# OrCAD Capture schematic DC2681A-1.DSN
size Custom
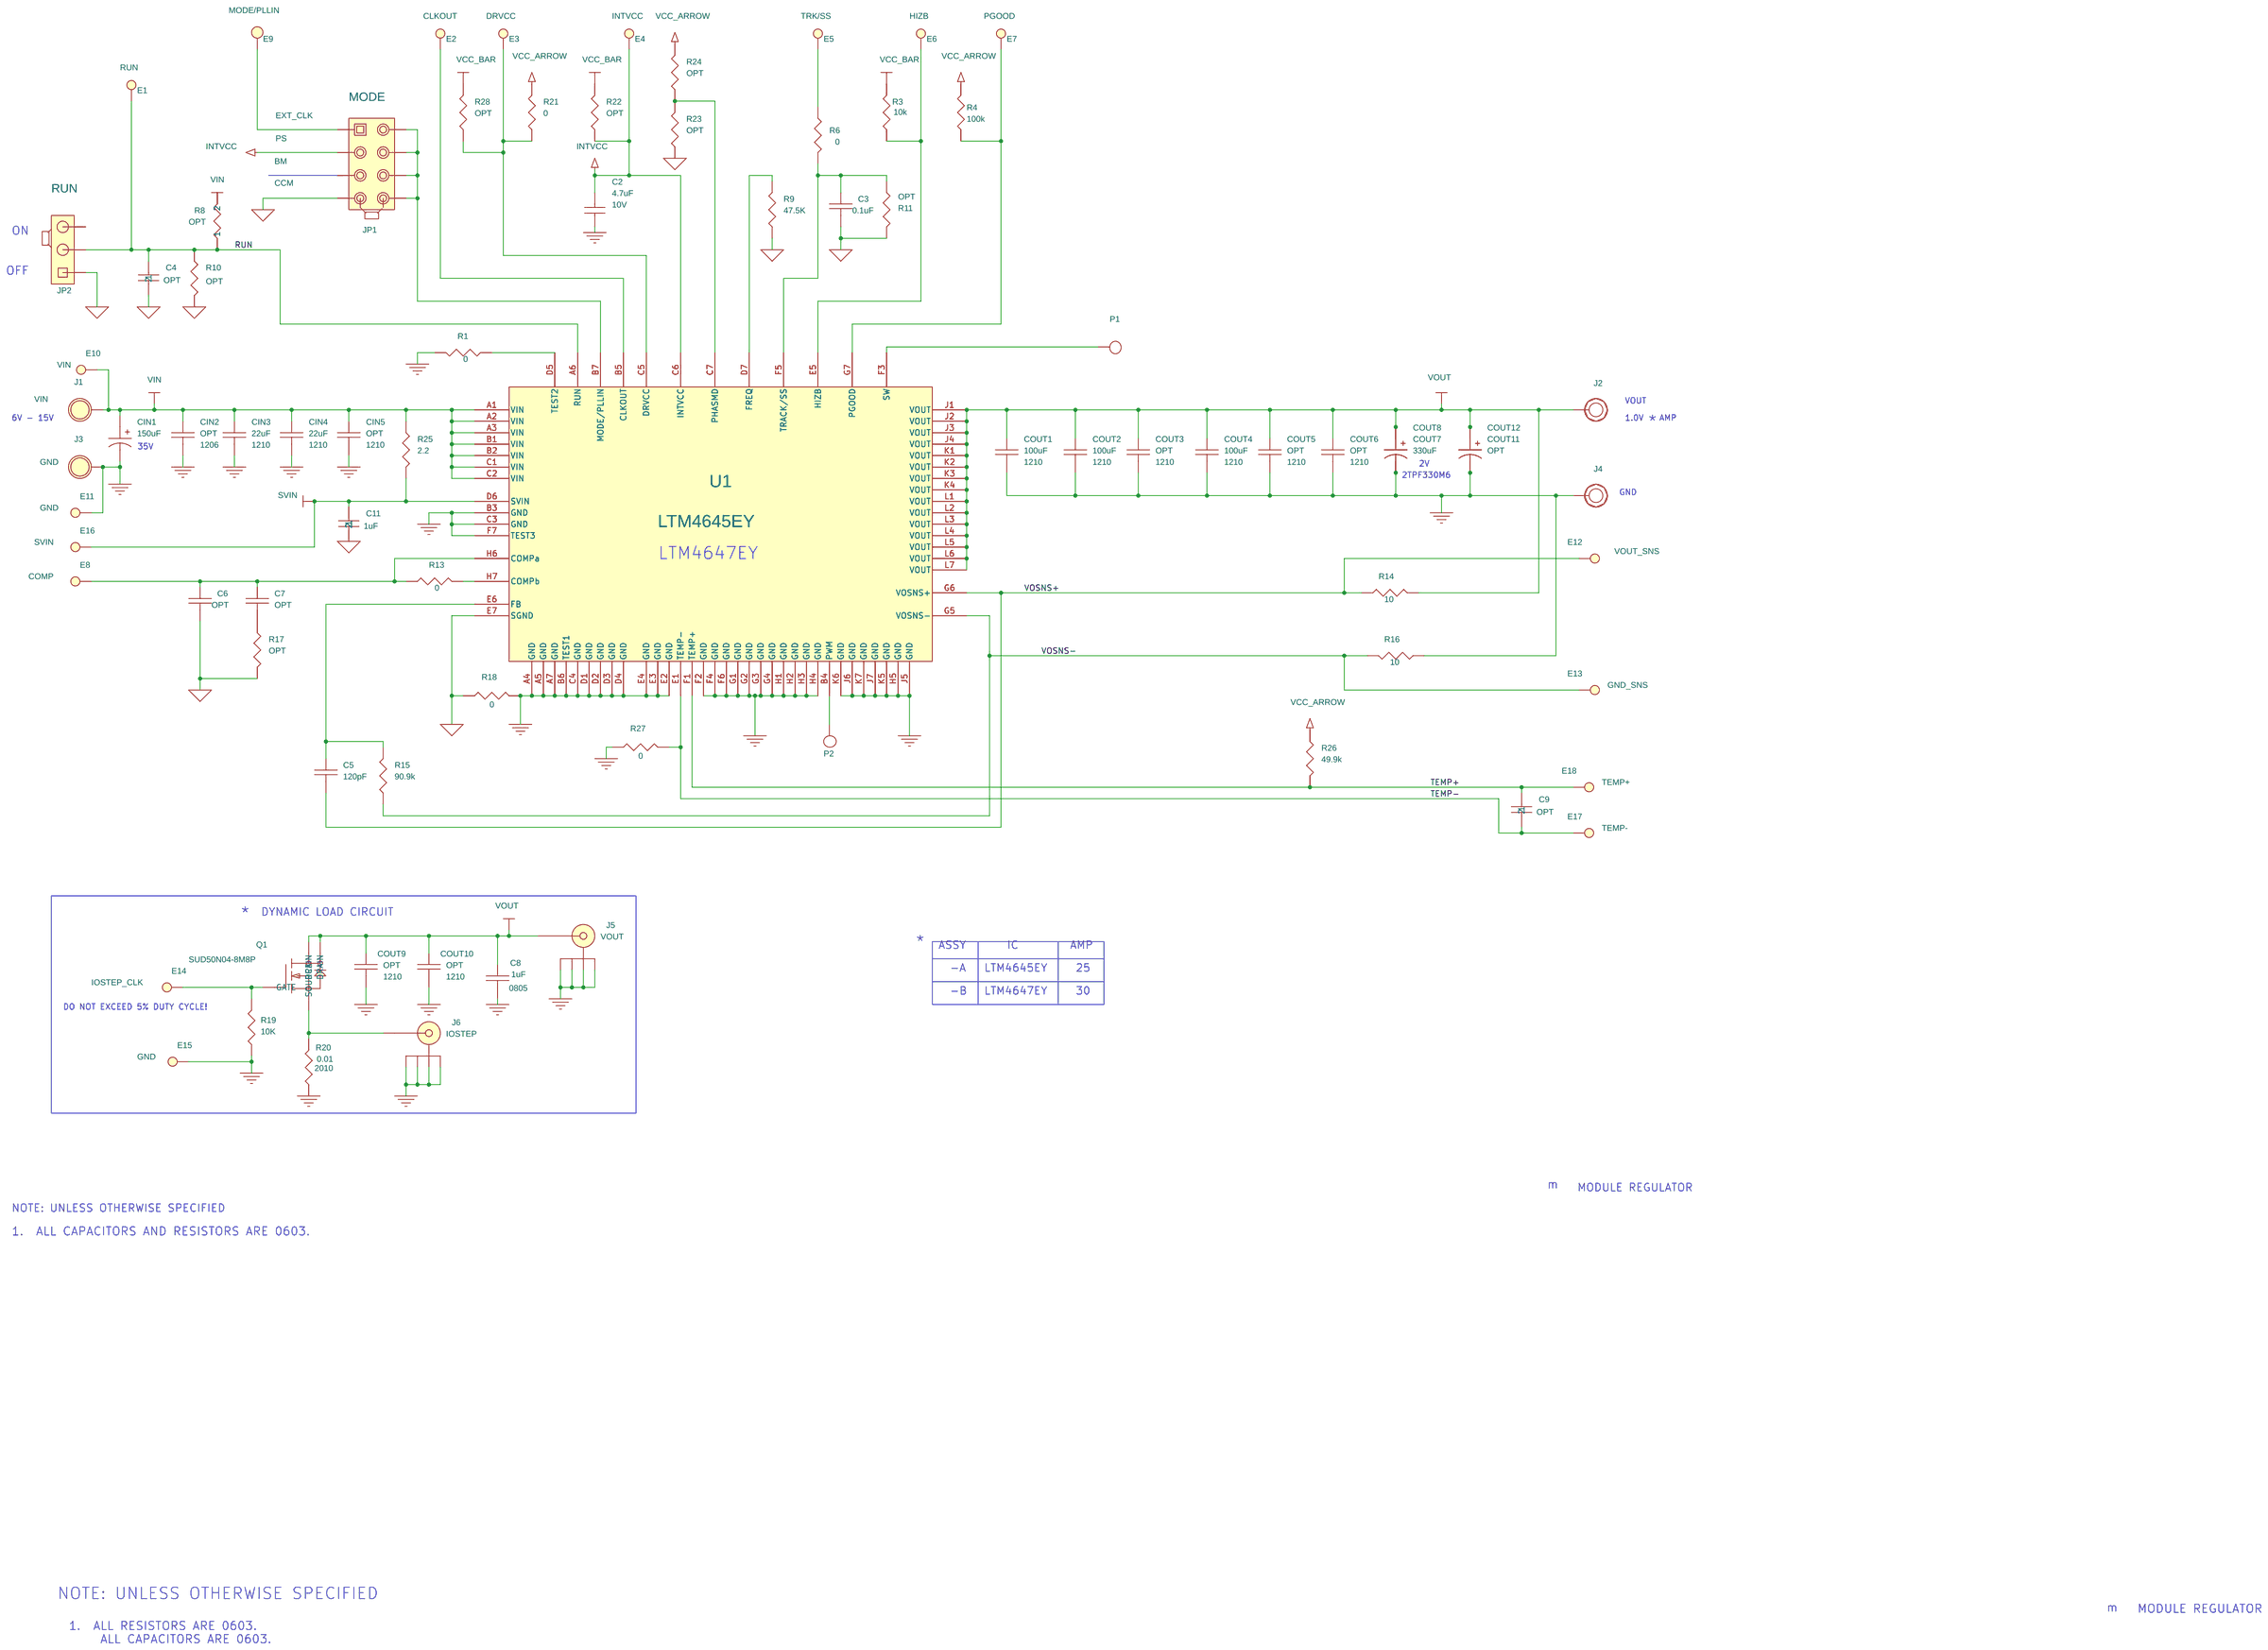
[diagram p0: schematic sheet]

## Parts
C2  4.7uF  [0603]
C3  0.1uF  [0603]
C4  OPT  [0603]
C5  120pF  [0603]
C6  OPT  [0603]
C7  OPT  [0603]
C8  1uF  [0805]
C9  OPT  [0603]
C11  1uF  [0603]
CIN1  150uF  [C-10X10.5]
CIN2  OPT  [1206]
CIN3  22uF  [1210]
CIN4  22uF  [1210]
CIN5  OPT  [1210]
COUT1  100uF  [1210]
COUT2  100uF  [1210]
COUT3  OPT  [1210]
COUT4  100uF  [1210]
COUT5  OPT  [1210]
COUT6  OPT  [1210]
COUT7  330uF  [C-D3L-D2E-D4]
COUT8  330uF  [C-D3L-D2E-D4]
COUT9  OPT  [1210]
COUT10  OPT  [1210]
COUT11  OPT  [C-D3L-D2E-D4]
COUT12  OPT  [C-D3L-D2E-D4]
E1  TURRETS  [MILL-MAX-2308]
E2  CLKOUT  [MILL-MAX-2308]
E3  DRVCC  [MILL-MAX-2308]
E4  INTVCC  [MILL-MAX-2308]
E5  TRK/SS  [MILL-MAX-2308]
E6  HIZB  [MILL-MAX-2308]
E7  PGOOD  [MILL-MAX-2308]
E8  COMP  [MILL-MAX-2308]
E9  MODE/PLLIN  [MILL-MAX-2308]
E10  TURRETS  [MILL-MAX-2308]
E11  GND  [MILL-MAX-2308]
E12  TURRETS  [MILL-MAX-2308]
E13  TURRETS  [MILL-MAX-2308]
E14  IOSTEP_CLK  [MILL-MAX-2308]
E15  GND  [MILL-MAX-2308]
E16  SVIN  [MILL-MAX-2308]
E17  TURRETS  [MILL-MAX-2308]
E18  TURRETS  [MILL-MAX-2308]
J1  BANANA SMALL  [KEY-575-4]
J2  STUD  [CON\LUG\10]
J3  BANANA SMALL  [KEY-575-4]
J4  STUD  [CON\LUG\10]
J5  VOUT  [BNC]
J6  IOSTEP  [BNC]
JP1  HD2X4-079  [HD2X4-079]
JP2  HD1X3-079  [HD1X3-079]
P1  SMD PAD  [PAD]
P2  SMD PAD  [PAD]
Q1  SUD50N04-8M8P  [TO252]
R1  0  [0603]
R3  10k  [0603]
R4  100k  [0603]
R6  0  [0603]
R8  OPT  [0603]
R9  47.5K  [0603]
R10  OPT  [0603]
R11  OPT  [0603]
R13  0  [0603]
R14  10  [0603]
R15  90.9k  [0603]
R16  10  [0603]
R17  OPT  [0603]
R18  0  [0603]
R19  10K  [0603]
R20  0.01  [2010]
R21  0  [0603]
R22  OPT  [0603]
R23  OPT  [0603]
R24  OPT  [0603]
R25  2.2  [0603]
R26  49.9k  [0603]
R27  0  [0603]
R28  OPT  [0603]
U1  LTM4645EY  [BGA77-15X9-5.01-A]
XJP1  2mm Ctrs.
XJP2  2mm Ctrs.

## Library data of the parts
C2 = CAP_NP_3: CAP, 0805 4.7uF 10% 10V X5R; Part Number: TAIYO YUDEN LMK212BJ475KG-T; Voltage: 10V
C3 C5-C7 = CAP0603_1: Component: cap; Manufacturer: TDK; Manufacturer P/N: C1608C0G1H102J; Tolerance: 5%; Type: cer 0603; Vendor: Digikey; Vendor P/N: 445-1293-1-ND; Volts/Amps/Watts: 50V
C4 = CAP_NP_1_1: CAP, 0603 0.1uF 10% 50V X7R; Part Number: TDK C1608X7R1H104K; Voltage: 50V
C8 = CAP0603_1
C9 = CAP_NP_1_2: CAP, 0603 0.1uF 10% 50V X7R; Part Number: TDK C1608X7R1H104K; Voltage: 50V
C11 = CAP_NP_1: CAP, 0603 0.1uF 10% 50V X7R; Part Number: TDK C1608X7R1H104K; Voltage: 50V
CIN1 = CAPR12X5_0: Component: cap; Manufacturer: SANYO; Tolerance: 20%; Type: OS-CON; Volts/Amps/Watts: 16V
CIN2-CIN5 = CAP1210_1: Component: cap; Manufacturer: Taiyo Yuden; Manufacturer P/N: GMK325BJ106KN-T; Tolerance: 10%; Type: cer 1210; Vendor: Digikey; Vendor P/N: 587-1439-1-ND; Volts/Amps/Watts: 25V
COUT1-COUT6 COUT9 COUT10 = CAP0603_1: Component: cap; Manufacturer: TDK; Manufacturer P/N: C3225X5R0J107M; Part Type: CAP1210; Tolerance: 20%; Type: cer 1210 X5R; Vendor: Digikey; Vendor P/N: 445-1437-1-ND; Volts/Amps/Watts: 6.3v
COUT7 COUT8 COUT11 COUT12 = CAPR12X5_0: Component: cap; Manufacturer: SANYO; Manufacturer P/N: 6TPF330M9L; Tolerance: 20%; Type: TANT; Volts/Amps/Watts: 6.3V
E1 = TURRETS_1: Component: tp; Label: RUN; Manufacturer: Keystone; Manufacturer P/N: 1593-2; Vendor: Digikey; Vendor P/N: 1593-2K-ND
E2-E8 E14 E16 = TURRETS_1: Component: tp; Label: GND; Manufacturer: Keystone; Manufacturer P/N: 1593-2; Vendor: Digikey; Vendor P/N: 1593-2K-ND
E9 = T_POINT_R_0: TURRET; Part Number: MILL-MAX 2501-2-00-80-00-00-07-0; STATUS: ?
E10 = TURRETS_1: Component: tp; Label: VIN; Manufacturer: Keystone; Manufacturer P/N: 1593-2; Vendor: Digikey; Vendor P/N: 1593-2K-ND
E11 E15 = TURRETS_1: Component: tp; Manufacturer: Keystone; Manufacturer P/N: 1593-2; Vendor: Digikey; Vendor P/N: 1593-2K-ND
E12 = TURRETS_1: Component: tp; Label: VOUT_SNS; Vendor: Digikey; Vendor P/N: 1593-2K-ND
E13 = TURRETS_1: Component: tp; Label: GND_SNS; Vendor: Digikey; Vendor P/N: 1593-2K-ND
E17 = TURRETS_1: Component: tp; Label: TEMP-; Vendor: Digikey; Vendor P/N: 1593-2K-ND
E18 = TURRETS_1: Component: tp; Label: TEMP+; Vendor: Digikey; Vendor P/N: 1593-2K-ND
J1 = BANANA_SMALL_0: Component: conn; Label: VIN
J2 J4 = E-KEY-575
J3 = BANANA_SMALL_0: Component: conn; Label: GND
J5 J6 = BNC5-SCH_0
JP1 = Samtec_TMM-103-02-L-D_0: 10th Part Field: PS; 11th Part Field: CCM; 12th Part Field: MODE; 9th Part Field: EXT_CLK; PIN5: BM
JP2 = Commcon2802s03g2_7: 11th Part Field: OFF; 12th Part Field: RUN; 9th Part Field: ON
P1 P2 = PAD_2: Component: tp; Label: <Label>; Vendor: Digikey; Vendor P/N: 1593-2K-ND
Q1 = IRF540_0
R1 R9 R13 R15 = RES0603_9: Manufacturer: Rohm; Manufacturer P/N: RHM0.0GCT-ND; Tolerance: 5%; Vendor: Digikey; Vendor P/N: RHM0.0GCT-ND; Volts/Amps/Watts: 0.1W
R3 R4 R21-R24 R28 = RES_0: RES, 0603 0 OHM JUMPER 1/10W; Part Number: VISHAY CRC06030000Z0EA; Tolerance: JUMPER
R6 R11 R17 R25 R26 = RES0603_9: Component: res; Label: <label>; Manufacturer: Panasonic; Manufacturer P/N: ERJ-3EKF5901V; Tolerance: 1%; Vendor: Digikey; Vendor P/N: P5.90KHCT-ND; Volts/Amps/Watts: 0.1W
R8 = CR16-104JM: RES, 0603 30.1k OHMS 1% 1/10W; Part Number: VISHAY CRCW060330K1FKEA
R10 = CR16-2002FM: RES, 0603 10.0k OHMS 1% 1/10W; 5th Part Field: CR16-1002FM; Part Number: VISHAY CRCW060330K1FKEA
R14 = RES0603_9: Manufacturer: Rohm; Manufacturer P/N: MCR03EZPFX1000; Vendor: Digikey; Vendor P/N: RHM100HCT-ND; Volts/Amps/Watts: 0.1W
R16 = RES0603_9: Manufacturer: Yageo; Manufacturer P/N: RC0603JR-070RL; Tolerance: 5%; Vendor: Digikey; Vendor P/N: 311-0.0GRCT-ND; Volts/Amps/Watts: 0.1W
R18 R27 = RES0603_3
R19 = RES0603_9
R20 = RES0603_5: Label: 1W; Manufacturer: VISHAY; Manufacturer P/N: CRCW251230R0JNEG; Part Type: 2512; Tolerance: 5%; Vendor: Digikey; Vendor P/N: 541-30XCT-ND; Volts/Amps/Watts: 0.1W
U1 = LTC3880-M0001_52: Component: IC; Manufacturer: LTC; Manufacturer P/N: LTC3880_M0001; Vendor: LTC; Vendor P/N: LTC3880_M0001
XJP1 XJP2 = CommconCCIJ2MM-138G

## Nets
GND_POWER: C2.2 C8.2 CIN1.2 CIN2.2 CIN3.2 CIN4.2 CIN5.2 COUT1.2 COUT2.2 COUT3.2 COUT4.2 COUT5.2 COUT6.2 COUT7.2 COUT8.2 COUT9.2 COUT10.2 COUT11.2 COUT12.2 E11.1(TP) E15.1(TP) J3.1(TP) J4.1 J5.2 J5.3 J5.4 J5.5 J6.2 J6.3 J6.4 J6.5 R1.2 R16.2 R18.2 R19.2 R20.1 R27.1 U1.A4(GND) U1.A5(GND) U1.A7(GND) U1.B3(GND) U1.B6(TEST1) U1.C3(GND) U1.C4(GND) U1.D1(GND) U1.D2(GND) U1.D3(GND) U1.D4(GND) U1.E2(GND) U1.E3(GND) U1.E4(GND) U1.F2(GND) U1.F4(GND) U1.F6(GND) U1.F7(TEST3) U1.G1(GND) U1.G2(GND) U1.G3(GND) U1.G4(GND) U1.H1(GND) U1.H2(GND) U1.H3(GND) U1.H4(GND) U1.H5(GND) U1.J5(GND) U1.J6(GND) U1.J7(GND) U1.K5(GND) U1.K6(GND) U1.K7(GND)
GND_SIGNAL: C3.2 C4.2 C6.2 C11.2 JP1.7 JP2.1 R9.2 R10.2 R11.2 R17.2 R18.1 R23.2 U1.E7(SGND)
SVIN: C11.1 E16.1(TP) R22.1 R25.2 U1.D6(SVIN)
VIN: CIN1.1 CIN2.1 CIN3.1 CIN4.1 CIN5.1 E10.1(TP) J1.1(TP) R3.1 R8.2 R25.1 R28.1 U1.A1(VIN) U1.A2(VIN) U1.A3(VIN) U1.B1(VIN) U1.B2(VIN) U1.C1(VIN) U1.C2(VIN)
INTVCC: C2.1 E4.1(TP) JP1.3 R4.1 R21.1 R22.2 R24.1 R26.1 U1.C6(INTVCC)
RUN: C4.1 E1.1(TP) JP2.2 R8.1 R10.1 U1.A6(RUN)
TEMP+: C9.1 E18.1(TP) R26.2 U1.F1(TEMP+)
TEMP-: C9.2 E17.1(TP) R27.2 U1.E1(TEMP-)
VOSNS+: C5.2 E12.1(TP) R14.1 U1.G6(VOSNS+)
VOSNS-: E13.1(TP) R15.1 R16.1 U1.G5(VOSNS-)
VOUT: C8.1 COUT1.1 COUT2.1 COUT3.1 COUT4.1 COUT5.1 COUT6.1 COUT7.1 COUT8.1 COUT9.1 COUT10.1 COUT11.1 COUT12.1 J2.1 J5.1 Q1.2(DRAIN) Q1.4(DRAIN) R14.2 U1.J1(VOUT) U1.J2(VOUT) U1.J3(VOUT) U1.J4(VOUT) U1.K1(VOUT) U1.K2(VOUT) U1.K3(VOUT) U1.K4(VOUT) U1.L1(VOUT) U1.L2(VOUT) U1.L3(VOUT) U1.L4(VOUT) U1.L5(VOUT) U1.L6(VOUT) U1.L7(VOUT)
N17156241: C6.1 C7.1 E8.1(TP) R13.2 U1.H6(COMPa)
N18445914: E14.1(TP) Q1.1(GATE) R19.1
N18446004: J6.1 Q1.3(SOURCE) R20.2
N18545248: JP1.2 JP1.4 JP1.6 JP1.8 U1.B7(MODE/PLLIN)
N18548537: E2.1(TP) U1.B5(CLKOUT)
N18603532: C3.1 R6.2 R11.1 U1.F5(TRACK/SS)
N18614805: E6.1(TP) R3.2 U1.E5(HIZB)
N18615386: E7.1(TP) R4.2 U1.G7(PGOOD)
N18638855: R23.1 R24.2 U1.C7(PHASMD)
N18652648: P1.1(TP) U1.F3(SW)
N18764356: E9.1(TP) JP1.1
N18853132: R9.1 U1.D7(FREQ)
N18884741: E5.1(TP) R6.1
N18910913: C5.1 R15.2 U1.E6(FB)
N19032140: P2.1(TP) U1.B4(PWM)
N19072015: E3.1(TP) R21.2 R28.2 U1.C5(DRVCC)
N19201331: R1.1 U1.D5(TEST2)
N19213489: R13.1 U1.H7(COMPb)
N19213545: C7.2 R17.1

Not connected (* = marked no-connect by the designer): JP1 5; JP2 3

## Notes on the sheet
- ON
- OFF
- VOUT
- 6V - 15V
- 1.0V
- *
- AMP
- 35V
- 2V
- 2TPF330M6
- GND
- LTM4647EY
- *
- DYNAMIC LOAD CIRCUIT
- *
- ASSY
- IC
- AMP
- -A
- LTM4645EY
- 25
- -B
- LTM4647EY
- 30
- DO NOT EXCEED 5% DUTY CYCLE!
- MODULE REGULATOR
- m
- NOTE: UNLESS OTHERWISE SPECIFIED
- 1.  ALL CAPACITORS AND RESISTORS ARE 0603.
- NOTE: UNLESS OTHERWISE SPECIFIED
- MODULE REGULATOR
- m
- 1.  ALL RESISTORS ARE 0603.
       ALL CAPACITORS ARE 0603.
